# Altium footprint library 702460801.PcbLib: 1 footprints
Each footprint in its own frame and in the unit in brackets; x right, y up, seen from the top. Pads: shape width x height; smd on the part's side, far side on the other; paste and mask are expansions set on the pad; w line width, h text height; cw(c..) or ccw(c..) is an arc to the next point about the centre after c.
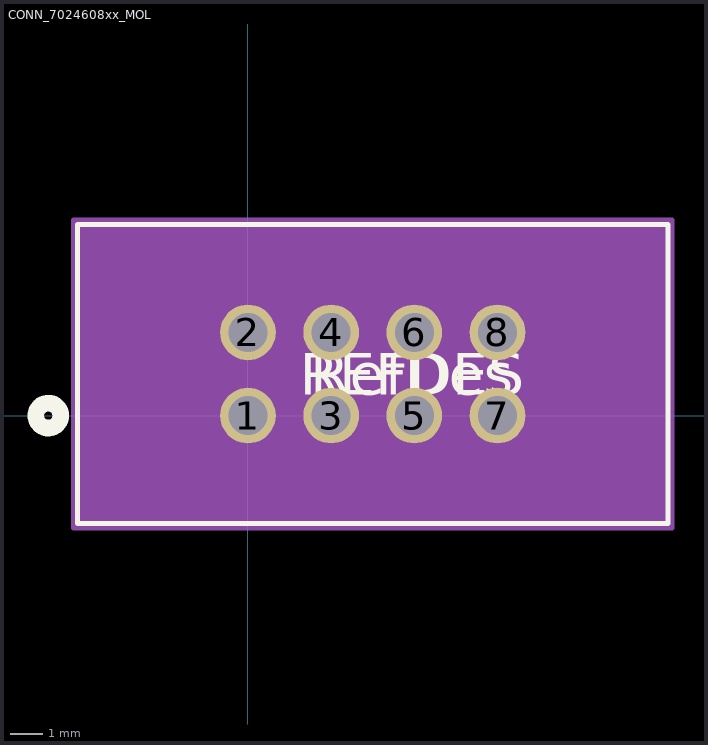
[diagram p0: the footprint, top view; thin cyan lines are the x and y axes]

## CONN_7024608xx_MOL [mil]
pads (8):
  round 67 / inner round 60 / far side round 67 hole 47 paste-33.5 mask+0: 1(0,0) 2(0,100) 3(100,0) 4(100,100) 5(200,0) 6(200,100) 7(300,0) 8(300,100)
Top Overlay:
  circle w20: c-240,0 r15
  lines w6: -205,-130 505,-130 505,230 -205,230 -205,-130
  text "RefDes" at 75,25 h50
  text "REFDES" at 62.5,25 h50
Bottom Overlay:
  circle w20: c-240,0 r15
Mechanical 13:
  circle w20: c0,0 r15
  lines w1: -200,-125 500,-125 500,225 -200,225 -200,-125
  text "RefDes2" at 62.5,25 h50
Mechanical 15:
  region: 510,235 -210,235 -210,-135 510,-135
  lines w6: -210,-135 -210,235 510,235 510,-135 -210,-135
